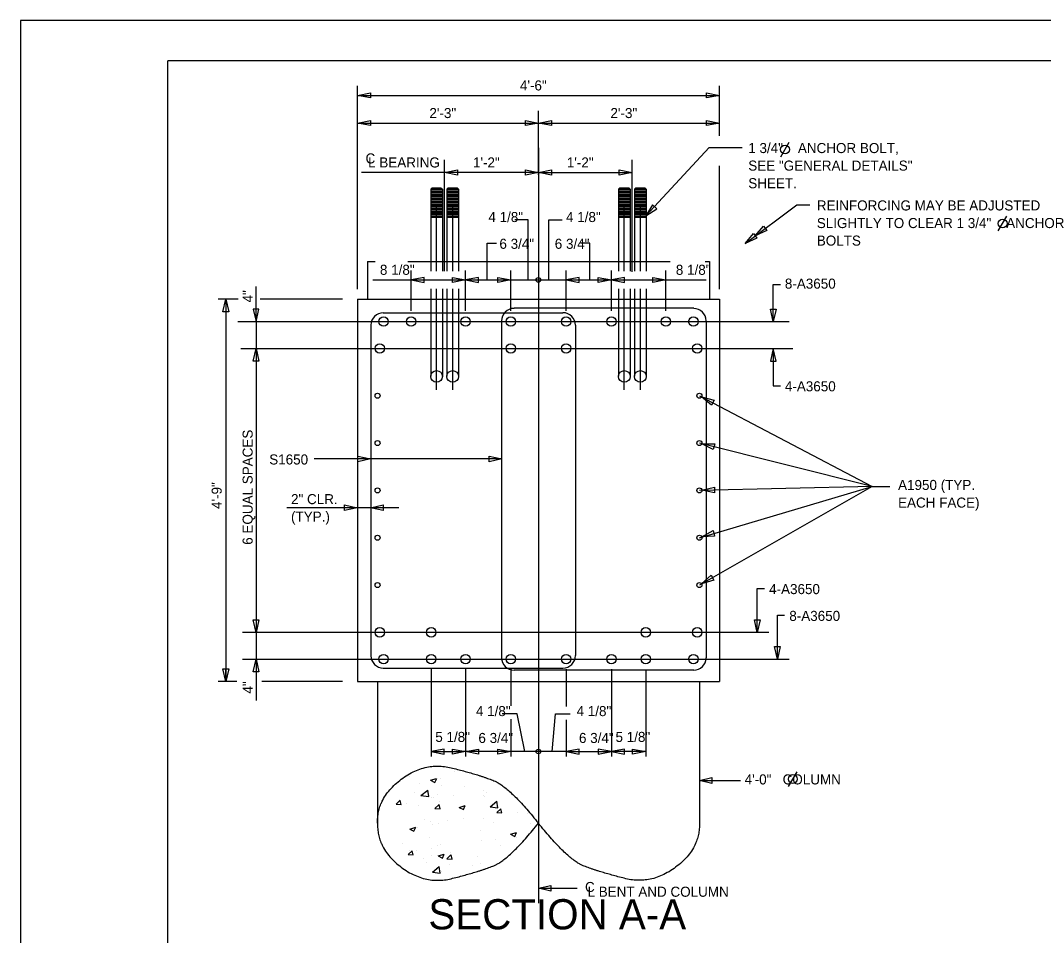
# Model space of a CAD drawing. Extents: x -133.1 to -97, y -1.7 to 20.3.
# Drawn here: x -133.14 to -120.43, y 8.94 to 20.31 of the extents above; entities that cross this region are included whole.
import ezdxf

# ---------------------------------------------------------------- set-up
doc = ezdxf.new("R2010")
doc.units = 0
for name, color, linetype in [('BR_AUTO DIMENSION', 7, 'Continuous'), ('BR_BORDER LINES', 7, 'Continuous'), ('BR_CENTER LINES', 7, 'Continuous'), ('BR_CONCRETE', 7, 'Continuous'), ('BR_REBAR', 7, 'Continuous'), ('BR_STRUCTURAL STEEL', 7, 'Continuous'), ('BR_TEXT', 7, 'Continuous'), ('Level 31', 7, 'Continuous')]:
    doc.layers.add(name, color=color, linetype=linetype)

msp = doc.modelspace()

# ---------------------------------------------------------------- linework, layer by layer
at = {"layer": 'BR_AUTO DIMENSION'}
for p, q in [((-128.953, 16.971), (-128.953, 19.496)), ((-124.453, 18.875), (-124.453, 19.496)), ((-128.953, 19.377), (-124.453, 19.377)), ((-126.703, 18.79), (-126.703, 19.188)), ((-126.703, 18.392), (-126.703, 19.136)), ((-126.703, 18.392), (-126.703, 19.136)), ((-128.953, 19.033), (-126.703, 19.033)), ((-126.703, 19.033), (-124.453, 19.033)), ((-125.367, 17.88), (-124.583, 18.729)), ((-124.583, 18.729), (-124.172, 18.729)), ((-127.869, 18.243), (-127.869, 18.575)), ((-125.536, 18.187), (-125.536, 18.575)), ((-124.453, 16.971), (-124.453, 18.501)), ((-127.869, 18.419), (-128.901, 18.419)), ((-126.703, 18.419), (-127.869, 18.419)), ((-126.703, 18.419), (-125.536, 18.419)), ((-126.832, 17.833), (-126.997, 17.833)), ((-126.832, 17.085), (-126.832, 17.833)), ((-126.573, 17.085), (-126.573, 17.833)), ((-126.573, 17.833), (-126.409, 17.833)), ((-127.342, 17.085), (-127.342, 17.54)), ((-127.342, 17.54), (-127.224, 17.54)), ((-126.063, 17.54), (-126.181, 17.54)), ((-126.063, 17.085), (-126.063, 17.54)), ((-128.286, 16.7), (-128.286, 17.203)), ((-127.609, 16.7), (-127.609, 17.203)), ((-127.046, 16.7), (-127.046, 17.203)), ((-126.359, 16.7), (-126.359, 17.203)), ((-125.796, 16.7), (-125.796, 17.203)), ((-125.119, 16.7), (-125.119, 17.203)), ((-128.763, 17.085), (-124.62, 17.085)), ((-130.213, 16.567), (-130.213, 17.003)), ((-130.435, 16.844), (-130.685, 16.844)), ((-130.588, 16.844), (-130.588, 12.094)), ((-129.14, 16.844), (-130.162, 16.844)), ((-130.213, 16.567), (-130.213, 11.857)), ((-124.703, 15.645), (-122.556, 14.517)), ((-122.556, 14.517), (-124.703, 15.057)), ((-127.159, 14.86), (-129.49, 14.86)), ((-122.556, 14.517), (-124.703, 13.293)), ((-122.556, 14.517), (-124.703, 14.469)), ((-124.703, 13.881), (-122.556, 14.517)), ((-122.556, 14.517), (-122.334, 14.517)), ((-128.438, 14.254), (-129.831, 14.254)), ((-128.036, 12.246), (-128.036, 11.161)), ((-127.609, 12.246), (-127.609, 11.161)), ((-127.046, 12.246), (-127.046, 11.79)), ((-126.359, 12.246), (-126.359, 11.784)), ((-125.796, 12.246), (-125.796, 11.161)), ((-125.369, 12.234), (-125.369, 11.161)), ((-130.452, 12.094), (-130.685, 12.094)), ((-129.14, 12.094), (-130.142, 12.094)), ((-126.703, 12.032), (-126.703, 11.161)), ((-126.969, 11.693), (-127.152, 11.693)), ((-127.046, 11.627), (-127.046, 11.161)), ((-127.046, 11.617), (-127.046, 11.161)), ((-126.874, 11.223), (-126.969, 11.693)), ((-126.531, 11.223), (-126.492, 11.693)), ((-126.492, 11.693), (-126.309, 11.693)), ((-126.359, 11.617), (-126.359, 11.161)), ((-128.036, 11.224), (-127.671, 11.224)), ((-127.871, 11.224), (-127.671, 11.224)), ((-127.046, 11.224), (-127.671, 11.224)), ((-127.046, 11.224), (-127.246, 11.224)), ((-126.703, 11.224), (-127.046, 11.224)), ((-126.846, 11.224), (-127.046, 11.224)), ((-126.359, 11.224), (-126.703, 11.224)), ((-126.359, 11.224), (-126.159, 11.224)), ((-126.359, 11.224), (-125.734, 11.224)), ((-125.369, 11.224), (-125.734, 11.224)), ((-125.534, 11.224), (-125.734, 11.224)), ((-124.703, 10.864), (-124.191, 10.864)), ((-126.703, 9.524), (-126.22, 9.524))]:
    msp.add_line(p, q, dxfattribs=at)
for points in [[(-128.79, 19.346), (-128.953, 19.377), (-128.79, 19.408)], [(-124.615, 19.408), (-124.453, 19.377), (-124.615, 19.346)], [(-128.79, 19.002), (-128.953, 19.033), (-128.79, 19.065)], [(-126.865, 19.065), (-126.703, 19.033), (-126.865, 19.002)], [(-126.54, 19.002), (-126.703, 19.033), (-126.54, 19.065)], [(-124.615, 19.065), (-124.453, 19.033), (-124.615, 19.002)], [(-127.707, 18.388), (-127.869, 18.419), (-127.707, 18.451)], [(-126.865, 18.451), (-126.703, 18.419), (-126.865, 18.388)], [(-126.54, 18.388), (-126.703, 18.419), (-126.54, 18.451)], [(-125.698, 18.451), (-125.536, 18.419), (-125.698, 18.388)], [(-125.285, 18.017), (-125.367, 17.88), (-125.233, 17.968)], [(-123.863, 17.697), (-124.009, 17.632), (-123.906, 17.754)], [(-123.988, 17.603), (-124.134, 17.539), (-124.031, 17.661)], [(-128.123, 17.116), (-128.286, 17.085), (-128.123, 17.054)], [(-127.771, 17.116), (-127.609, 17.085), (-127.771, 17.054)], [(-127.446, 17.116), (-127.609, 17.085), (-127.446, 17.054)], [(-127.209, 17.116), (-127.046, 17.085), (-127.209, 17.054)], [(-126.196, 17.116), (-126.359, 17.085), (-126.196, 17.054)], [(-125.959, 17.116), (-125.796, 17.085), (-125.959, 17.054)], [(-125.634, 17.116), (-125.796, 17.085), (-125.634, 17.054)], [(-125.282, 17.116), (-125.119, 17.085), (-125.282, 17.054)], [(-130.624, 16.688), (-130.588, 16.844), (-130.552, 16.688)], [(-130.249, 16.723), (-130.213, 16.567), (-130.177, 16.723)], [(-123.748, 16.723), (-123.784, 16.567), (-123.82, 16.723)], [(-130.249, 16.077), (-130.213, 16.233), (-130.177, 16.077)], [(-123.748, 16.077), (-123.784, 16.233), (-123.82, 16.077)], [(-124.552, 15.528), (-124.675, 15.631), (-124.52, 15.592)], [(-124.53, 14.976), (-124.672, 15.049), (-124.512, 15.046)], [(-128.946, 14.896), (-128.79, 14.86), (-128.946, 14.824)], [(-127.315, 14.896), (-127.159, 14.86), (-127.315, 14.824)], [(-124.515, 14.437), (-124.671, 14.47), (-124.516, 14.509)], [(-129.113, 14.29), (-128.957, 14.254), (-129.113, 14.218)], [(-128.634, 14.218), (-128.79, 14.254), (-128.634, 14.29)], [(-124.513, 13.9), (-124.673, 13.89), (-124.533, 13.969)], [(-124.522, 13.354), (-124.675, 13.308), (-124.558, 13.417)], [(-130.177, 12.861), (-130.213, 12.705), (-130.249, 12.861)], [(-123.947, 12.861), (-123.983, 12.705), (-124.019, 12.861)], [(-123.697, 12.528), (-123.733, 12.372), (-123.769, 12.528)], [(-130.249, 12.216), (-130.213, 12.372), (-130.177, 12.216)], [(-130.552, 12.25), (-130.588, 12.094), (-130.624, 12.25)], [(-127.873, 11.255), (-128.036, 11.224), (-127.873, 11.193)], [(-127.771, 11.255), (-127.609, 11.224), (-127.771, 11.193)], [(-127.446, 11.193), (-127.609, 11.224), (-127.446, 11.255)], [(-127.209, 11.255), (-127.046, 11.224), (-127.209, 11.193)], [(-126.196, 11.255), (-126.359, 11.224), (-126.196, 11.193)], [(-125.959, 11.193), (-125.796, 11.224), (-125.959, 11.255)], [(-125.634, 11.255), (-125.796, 11.224), (-125.634, 11.193)], [(-125.532, 11.255), (-125.369, 11.224), (-125.532, 11.193)], [(-124.547, 10.828), (-124.703, 10.864), (-124.547, 10.9)], [(-126.547, 9.488), (-126.703, 9.524), (-126.547, 9.56)]]:
    msp.add_lwpolyline(points, close=True, dxfattribs=at)
for points in [[(-124.134, 17.539), (-123.493, 18.018), (-123.328, 18.018)], [(-123.784, 16.567), (-123.784, 17.029), (-123.696, 17.029)], [(-123.784, 16.233), (-123.784, 15.77), (-123.696, 15.77)], [(-123.983, 12.705), (-123.983, 13.251), (-123.895, 13.251)], [(-123.733, 12.372), (-123.733, 12.918), (-123.645, 12.918)]]:
    msp.add_lwpolyline(points, dxfattribs=at)
for centre in [(-126.703, 17.085), (-126.703, 11.224)]:
    msp.add_circle(centre, 0.0285, dxfattribs=at)
at = {"layer": 'BR_BORDER LINES'}
for p in [(-97.642, 19.809), (-131.308, -1.191)]:
    msp.add_line(p, (-131.308, 19.809), dxfattribs=at)
at = {"layer": 'BR_CENTER LINES'}
for p, q in [((-126.703, 18.727), (-126.703, 9.34)), ((-127.869, 17.192), (-127.869, 18.575)), ((-125.536, 17.192), (-125.536, 18.575)), ((-127.969, 17.192), (-127.969, 18.017)), ((-127.769, 17.192), (-127.769, 18.017)), ((-125.636, 17.192), (-125.636, 18.017)), ((-125.436, 17.192), (-125.436, 18.017)), ((-125.536, 17.186), (-125.536, 17.206)), ((-127.969, 15.718), (-127.969, 16.974)), ((-127.769, 15.718), (-127.769, 16.974)), ((-125.636, 15.718), (-125.636, 16.974)), ((-125.436, 15.718), (-125.436, 16.974)), ((-130.438, 16.567), (-123.587, 16.567)), ((-130.404, 16.233), (-123.54, 16.233)), ((-123.838, 12.705), (-130.38, 12.705)), ((-130.38, 12.372), (-123.587, 12.372))]:
    msp.add_line(p, q, dxfattribs=at)
at = {"layer": 'BR_CONCRETE'}
for p, q in [((-128.828, 17.312), (-128.732, 17.312)), ((-128.828, 17.312), (-128.828, 16.844)), ((-128.326, 17.312), (-125.065, 17.312)), ((-124.63, 17.312), (-124.578, 17.312)), ((-124.578, 17.312), (-124.578, 16.844)), ((-128.953, 16.844), (-128.953, 12.094)), ((-128.953, 16.844), (-124.453, 16.844)), ((-124.453, 16.844), (-124.453, 12.094)), ((-128.953, 12.094), (-124.453, 12.094)), ((-128.703, 12.094), (-128.703, 10.302)), ((-124.703, 12.094), (-124.703, 10.303)), ((-127.746, 10.98), (-127.746, 10.98)), ((-128.304, 10.91), (-128.304, 10.91)), ((-128.178, 10.829), (-128.178, 10.829)), ((-128.043, 10.866), (-127.968, 10.888)), ((-128.043, 10.866), (-127.989, 10.838)), ((-127.989, 10.838), (-127.967, 10.888)), ((-127.922, 10.883), (-127.922, 10.883)), ((-128.248, 10.71), (-128.248, 10.71)), ((-128.163, 10.676), (-128.079, 10.743)), ((-128.067, 10.664), (-128.079, 10.743)), ((-127.962, 10.691), (-127.962, 10.691)), ((-127.902, 10.803), (-127.902, 10.803)), ((-127.616, 10.784), (-127.616, 10.784)), ((-127.382, 10.739), (-127.382, 10.739)), ((-127.354, 10.72), (-127.354, 10.72)), ((-128.473, 10.57), (-128.421, 10.618)), ((-128.473, 10.57), (-128.409, 10.565)), ((-128.409, 10.565), (-128.421, 10.617)), ((-128.419, 10.582), (-128.419, 10.582)), ((-128.346, 10.572), (-128.346, 10.572)), ((-128.163, 10.676), (-128.067, 10.664)), ((-128.028, 10.651), (-128.028, 10.651)), ((-128.007, 10.656), (-128.007, 10.656)), ((-127.99, 10.517), (-127.938, 10.565)), ((-127.926, 10.513), (-127.938, 10.565)), ((-127.935, 10.605), (-127.935, 10.605)), ((-127.76, 10.678), (-127.76, 10.678)), ((-127.39, 10.672), (-127.39, 10.672)), ((-127.379, 10.668), (-127.379, 10.668)), ((-127.305, 10.538), (-127.221, 10.605)), ((-127.209, 10.526), (-127.221, 10.605)), ((-128.191, 10.552), (-128.191, 10.552)), ((-127.99, 10.517), (-127.926, 10.513)), ((-127.689, 10.53), (-127.614, 10.552)), ((-127.689, 10.53), (-127.635, 10.502)), ((-127.635, 10.502), (-127.614, 10.552)), ((-127.305, 10.538), (-127.209, 10.526)), ((-127.221, 10.465), (-127.17, 10.513)), ((-127.221, 10.465), (-127.157, 10.461)), ((-127.157, 10.461), (-127.17, 10.513)), ((-126.959, 10.461), (-126.959, 10.461)), ((-126.842, 10.449), (-126.842, 10.449)), ((-128.115, 10.379), (-128.115, 10.379)), ((-128.041, 10.35), (-128.041, 10.35)), ((-128.024, 10.322), (-128.024, 10.322)), ((-127.948, 10.328), (-127.948, 10.328)), ((-127.829, 10.361), (-127.829, 10.361)), ((-127.636, 10.391), (-127.636, 10.391)), ((-127.392, 10.39), (-127.392, 10.39)), ((-127.257, 10.342), (-127.257, 10.342)), ((-126.802, 10.325), (-126.802, 10.325)), ((-128.303, 10.261), (-128.228, 10.284)), ((-128.303, 10.261), (-128.25, 10.233)), ((-128.25, 10.233), (-128.228, 10.284)), ((-128.204, 10.274), (-128.204, 10.274)), ((-127.427, 10.242), (-127.427, 10.242)), ((-127.049, 10.195), (-126.974, 10.217)), ((-127.049, 10.195), (-126.996, 10.167)), ((-126.996, 10.166), (-126.974, 10.217)), ((-128.391, 10.075), (-128.391, 10.075)), ((-128.052, 10.158), (-128.052, 10.158)), ((-127.961, 10.05), (-127.961, 10.05)), ((-127.917, 10.063), (-127.917, 10.063)), ((-127.405, 10.113), (-127.405, 10.113)), ((-127.241, 10.132), (-127.241, 10.132)), ((-127.17, 10.059), (-127.17, 10.059)), ((-126.973, 10.159), (-126.973, 10.159)), ((-126.855, 10.172), (-126.855, 10.172)), ((-128.324, 9.943), (-128.272, 9.991)), ((-128.324, 9.954), (-128.324, 9.954)), ((-128.324, 9.943), (-128.26, 9.938)), ((-128.306, 9.994), (-128.306, 9.994)), ((-128.26, 9.938), (-128.272, 9.991)), ((-128.217, 9.997), (-128.217, 9.997)), ((-128.038, 10.021), (-128.038, 10.021)), ((-128.038, 9.935), (-128.038, 9.935)), ((-127.949, 9.926), (-127.874, 9.948)), ((-127.949, 9.926), (-127.896, 9.898)), ((-127.896, 9.898), (-127.874, 9.948)), ((-127.841, 9.89), (-127.79, 9.938)), ((-127.795, 9.975), (-127.795, 9.975)), ((-127.777, 9.886), (-127.789, 9.938)), ((-128.134, 9.892), (-128.134, 9.892)), ((-128.098, 9.842), (-128.098, 9.842)), ((-128.021, 9.726), (-127.937, 9.794)), ((-127.925, 9.714), (-127.937, 9.794)), ((-127.841, 9.89), (-127.777, 9.886)), ((-127.812, 9.823), (-127.812, 9.823)), ((-127.523, 9.803), (-127.523, 9.803)), ((-127.466, 9.916), (-127.466, 9.916)), ((-127.418, 9.835), (-127.418, 9.835)), ((-128.021, 9.726), (-127.925, 9.714)), ((-127.974, 9.773), (-127.974, 9.773)), ((-127.914, 9.734), (-127.914, 9.734))]:
    msp.add_line(p, q, dxfattribs=at)
for centre in [(-128.703, 15.645), (-124.703, 15.645), (-128.703, 15.057), (-124.703, 15.057), (-128.703, 14.469), (-124.703, 14.469), (-128.703, 13.881), (-124.703, 13.881), (-128.703, 13.293), (-124.703, 13.293)]:
    msp.add_circle(centre, 0.0313, dxfattribs=at)
for points in [[(-128.703, 10.333), (-128.712, 10.649), (-128.113, 11.103), (-127.453, 10.939), (-127.064, 10.784), (-126.703, 10.333)], [(-128.703, 10.333), (-128.712, 10.017), (-128.113, 9.563), (-127.453, 9.727), (-127.064, 9.882), (-126.703, 10.333)], [(-124.702, 10.333), (-124.693, 10.017), (-125.292, 9.563), (-125.952, 9.727), (-126.341, 9.882), (-126.703, 10.333)]]:
    msp.add_open_spline(points, degree=2, dxfattribs=at)
at = {"layer": 'BR_REBAR'}
for p, q in [((-128.632, 16.677), (-126.4, 16.677)), ((-124.773, 16.732), (-127.005, 16.732)), ((-127.161, 16.575), (-127.161, 12.39)), ((-124.619, 16.573), (-124.619, 12.388)), ((-128.786, 16.523), (-128.786, 12.415)), ((-126.244, 16.521), (-126.244, 12.417)), ((-128.632, 12.261), (-126.4, 12.261)), ((-124.773, 12.234), (-127.005, 12.234))]:
    msp.add_line(p, q, dxfattribs=at)
for centre, radius in [((-128.628, 16.567), 0.0587), ((-128.286, 16.567), 0.0588), ((-127.609, 16.567), 0.0588), ((-127.046, 16.567), 0.0588), ((-126.359, 16.567), 0.0588), ((-125.796, 16.567), 0.0588), ((-125.119, 16.567), 0.0588), ((-124.777, 16.567), 0.0588), ((-128.675, 16.233), 0.0588), ((-127.046, 16.233), 0.0588), ((-126.359, 16.233), 0.0588), ((-124.73, 16.233), 0.0588), ((-128.675, 12.705), 0.0588), ((-128.036, 12.705), 0.0588), ((-125.369, 12.705), 0.0588), ((-124.73, 12.705), 0.0588), ((-128.628, 12.372), 0.0588), ((-128.036, 12.372), 0.0588), ((-127.609, 12.372), 0.0588), ((-127.046, 12.372), 0.0588), ((-126.359, 12.372), 0.0588), ((-125.796, 12.372), 0.0588), ((-125.369, 12.372), 0.0588), ((-124.777, 12.372), 0.0588)]:
    msp.add_circle(centre, radius, dxfattribs=at)
for centre, start, end in [((-128.63, 16.521), 91.025, 178.975), ((-127.005, 16.575), 90, 180), ((-126.4, 16.521), 0, 90), ((-124.775, 16.575), 1.025, 88.975), ((-128.63, 12.417), 181.025, 268.975), ((-127.005, 12.39), 180, 270), ((-126.4, 12.417), 270, 0), ((-124.775, 12.39), 271.025, 358.975)]:
    msp.add_arc(centre, 0.156, start, end, dxfattribs=at)
at = {"layer": 'BR_STRUCTURAL STEEL'}
for p, q in [((-128.042, 18.211), (-128.024, 18.229)), ((-128.042, 18.211), (-127.896, 18.211)), ((-128.042, 18.211), (-128.042, 17.312)), ((-128.042, 18.192), (-127.896, 18.192)), ((-128.024, 18.229), (-127.915, 18.229)), ((-127.915, 18.229), (-127.896, 18.211)), ((-127.896, 18.211), (-127.896, 17.312)), ((-127.842, 18.211), (-127.824, 18.229)), ((-127.842, 18.211), (-127.696, 18.211)), ((-127.842, 18.211), (-127.842, 17.312)), ((-127.842, 18.192), (-127.696, 18.192)), ((-127.824, 18.229), (-127.715, 18.229)), ((-127.715, 18.229), (-127.696, 18.211)), ((-127.696, 18.211), (-127.696, 17.312)), ((-125.709, 18.211), (-125.691, 18.229)), ((-125.709, 18.211), (-125.563, 18.211)), ((-125.709, 18.211), (-125.709, 17.192)), ((-125.709, 18.192), (-125.563, 18.192)), ((-125.691, 18.229), (-125.581, 18.229)), ((-125.581, 18.229), (-125.563, 18.211)), ((-125.563, 18.211), (-125.563, 17.192)), ((-125.509, 18.211), (-125.491, 18.229)), ((-125.509, 18.211), (-125.363, 18.211)), ((-125.509, 18.211), (-125.509, 17.192)), ((-125.509, 18.192), (-125.363, 18.192)), ((-125.491, 18.229), (-125.381, 18.229)), ((-125.381, 18.229), (-125.363, 18.211)), ((-125.363, 18.211), (-125.363, 17.192)), ((-128.042, 18.174), (-127.896, 18.174)), ((-128.042, 18.156), (-127.896, 18.156)), ((-128.042, 18.138), (-127.896, 18.138)), ((-128.042, 18.12), (-127.896, 18.12)), ((-128.042, 18.101), (-127.896, 18.101)), ((-128.042, 18.083), (-127.896, 18.083)), ((-128.042, 18.065), (-127.896, 18.065)), ((-127.842, 18.174), (-127.696, 18.174)), ((-127.842, 18.156), (-127.696, 18.156)), ((-127.842, 18.138), (-127.696, 18.138)), ((-127.842, 18.12), (-127.696, 18.12)), ((-127.842, 18.101), (-127.696, 18.101)), ((-127.842, 18.083), (-127.696, 18.083)), ((-127.842, 18.065), (-127.696, 18.065)), ((-125.709, 18.174), (-125.563, 18.174)), ((-125.709, 18.156), (-125.563, 18.156)), ((-125.709, 18.138), (-125.563, 18.138)), ((-125.709, 18.12), (-125.563, 18.12)), ((-125.709, 18.101), (-125.563, 18.101)), ((-125.709, 18.083), (-125.563, 18.083)), ((-125.709, 18.065), (-125.563, 18.065)), ((-125.509, 18.174), (-125.363, 18.174)), ((-125.509, 18.156), (-125.363, 18.156)), ((-125.509, 18.138), (-125.363, 18.138)), ((-125.509, 18.12), (-125.363, 18.12)), ((-125.509, 18.101), (-125.363, 18.101)), ((-125.509, 18.083), (-125.363, 18.083)), ((-125.509, 18.065), (-125.363, 18.065)), ((-128.042, 18.047), (-127.896, 18.047)), ((-128.042, 18.028), (-127.896, 18.028)), ((-128.042, 18.01), (-127.896, 18.01)), ((-128.042, 17.992), (-127.896, 17.992)), ((-128.042, 17.974), (-127.896, 17.974)), ((-128.042, 17.956), (-127.896, 17.956)), ((-128.042, 17.937), (-127.896, 17.937)), ((-127.842, 18.047), (-127.696, 18.047)), ((-127.842, 18.028), (-127.696, 18.028)), ((-127.842, 18.01), (-127.696, 18.01)), ((-127.842, 17.992), (-127.696, 17.992)), ((-127.842, 17.974), (-127.696, 17.974)), ((-127.842, 17.956), (-127.696, 17.956)), ((-127.842, 17.937), (-127.696, 17.937)), ((-125.709, 18.047), (-125.563, 18.047)), ((-125.709, 18.028), (-125.563, 18.028)), ((-125.709, 18.01), (-125.563, 18.01)), ((-125.709, 17.992), (-125.563, 17.992)), ((-125.709, 17.974), (-125.563, 17.974)), ((-125.709, 17.956), (-125.563, 17.956)), ((-125.709, 17.937), (-125.563, 17.937)), ((-125.509, 18.047), (-125.363, 18.047)), ((-125.509, 18.028), (-125.363, 18.028)), ((-125.509, 18.01), (-125.363, 18.01)), ((-125.509, 17.992), (-125.363, 17.992)), ((-125.509, 17.974), (-125.363, 17.974)), ((-125.509, 17.956), (-125.363, 17.956)), ((-125.509, 17.937), (-125.363, 17.937)), ((-128.042, 17.919), (-127.896, 17.919)), ((-128.042, 17.901), (-127.896, 17.901)), ((-128.042, 17.883), (-127.896, 17.883)), ((-128.042, 17.864), (-127.896, 17.864)), ((-127.842, 17.919), (-127.696, 17.919)), ((-127.842, 17.901), (-127.696, 17.901)), ((-127.842, 17.883), (-127.696, 17.883)), ((-127.842, 17.864), (-127.696, 17.864)), ((-125.709, 17.919), (-125.563, 17.919)), ((-125.709, 17.901), (-125.563, 17.901)), ((-125.709, 17.883), (-125.563, 17.883)), ((-125.709, 17.864), (-125.563, 17.864)), ((-125.509, 17.919), (-125.363, 17.919)), ((-125.509, 17.901), (-125.363, 17.901)), ((-125.509, 17.883), (-125.363, 17.883)), ((-125.509, 17.864), (-125.363, 17.864)), ((-128.042, 17.312), (-128.042, 17.192)), ((-127.896, 17.312), (-127.896, 17.192)), ((-127.842, 17.312), (-127.842, 17.192)), ((-127.696, 17.312), (-127.696, 17.192)), ((-125.709, 17.312), (-125.709, 17.252)), ((-125.563, 17.312), (-125.563, 17.244)), ((-125.509, 17.312), (-125.509, 17.247)), ((-125.363, 17.312), (-125.363, 17.262)), ((-128.042, 16.974), (-128.042, 15.888)), ((-127.896, 16.974), (-127.896, 15.885)), ((-127.842, 16.974), (-127.842, 15.888)), ((-127.696, 16.974), (-127.696, 15.885)), ((-125.709, 16.974), (-125.709, 15.888)), ((-125.563, 16.974), (-125.563, 15.885)), ((-125.509, 16.974), (-125.509, 15.888)), ((-125.363, 16.974), (-125.363, 15.885))]:
    msp.add_line(p, q, dxfattribs=at)
for centre in [(-127.969, 15.885), (-127.769, 15.885), (-125.636, 15.885), (-125.436, 15.885)]:
    msp.add_circle(centre, 0.0729, dxfattribs=at)
at = {"layer": 'BR_TEXT'}
for p, q in [((-123.69, 18.614), (-123.585, 18.795)), ((-120.987, 17.695), (-120.882, 17.877)), ((-130.588, 12.094), (-130.588, 12.242)), ((-123.593, 10.791), (-123.488, 10.973))]:
    msp.add_line(p, q, dxfattribs=at)
for centre in [(-123.638, 18.705), (-120.934, 17.786), (-123.541, 10.882)]:
    msp.add_circle(centre, 0.055, dxfattribs=at)
at = {"layer": 'Level 31'}
msp.add_lwpolyline([(-133.141, -1.691), (-97.141, -1.691), (-97.141, 20.309), (-133.141, 20.309)], close=True, dxfattribs=at)

# ---------------------------------------------------------------- texts
at = {"layer": 'BR_AUTO DIMENSION'}
for s, p in [('4\'-6"', (-126.933, 19.439)), ('2\'-3"', (-128.058, 19.096)), ('2\'-3"', (-125.808, 19.096)), ('C', (-128.852, 18.532)), ('L BEARING', (-128.82, 18.482)), ('1\'-2"', (-127.517, 18.482)), ('1\'-2"', (-126.35, 18.482)), ('4 1/8"', (-127.325, 17.804)), ('4 1/8"', (-126.36, 17.804)), ('6 3/4"', (-127.188, 17.471)), ('6 3/4"', (-126.5, 17.471)), ('8 1/8"', (-128.673, 17.148)), ('8 1/8"', (-124.995, 17.148)), ('4 1/8"', (-127.48, 11.664)), ('4 1/8"', (-126.229, 11.664)), ('5 1/8"', (-127.985, 11.343)), ('6 3/4"', (-127.449, 11.33)), ('6 3/4"', (-126.199, 11.33)), ('5 1/8"', (-125.745, 11.343))]:
    msp.add_text(s, height=0.125, dxfattribs=at).set_placement(p)
for p in [(-130.253, 16.805), (-130.253, 11.944)]:
    msp.add_text('4"', height=0.125, rotation=90, dxfattribs=at).set_placement(p)
at = {"layer": 'BR_TEXT'}
for s, rotation, p in [('1 3/4"    ANCHOR BOLT, ', 360, (-124.095, 18.661)), ('SEE "GENERAL DETAILS"', 360, (-124.095, 18.443)), ('SHEET.', 360, (-124.095, 18.224)), ('REINFORCING MAY BE ADJUSTED', 360, (-123.243, 17.948)), ('SLIGHTLY TO CLEAR 1 3/4"    ANCHOR', 360, (-123.243, 17.729)), ('BOLTS', 360, (-123.243, 17.511)), ('8-A3650', 360, (-123.64, 16.976)), ('4-A3650', 360, (-123.64, 15.7)), ('6 EQUAL SPACES', 90, (-130.255, 13.793)), ('S1650', 360, (-130.049, 14.791)), ('4\'-9"', 90, (-130.64, 14.238)), ('A1950 (TYP.', 360, (-122.233, 14.474)), ('2" CLR.', 360, (-129.778, 14.298)), ('EACH FACE)', 360, (-122.233, 14.255)), ('(TYP.)', 360, (-129.778, 14.08)), ('4-A3650', 360, (-123.836, 13.18)), ('8-A3650', 360, (-123.585, 12.847)), ('4\'-0"   COLUMN', 360, (-124.14, 10.815)), ('C', 360, (-126.124, 9.478)), ('L BENT AND COLUMN', 360, (-126.093, 9.419))]:
    msp.add_text(s, height=0.125, rotation=rotation, dxfattribs=at).set_placement(p)
msp.add_text('SECTION A-A', height=0.375, dxfattribs=at).set_placement((-128.071, 9.014))

doc.saveas('drawing.dxf')
